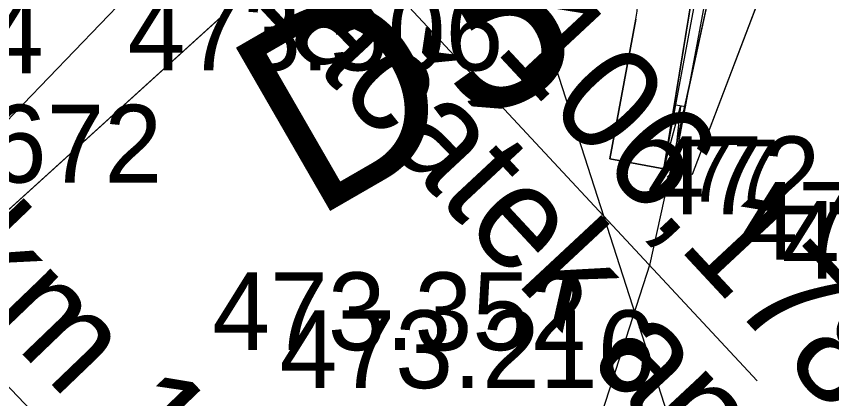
# Model space of a CAD drawing. Extents: x -758836 to -757729, y -1175316 to -1174366.
# Drawn here: x -758407.11 to -758394.53, y -1174860.8 to -1174854.9 of the extents above; entities that cross this region are included whole.
import ezdxf

# ---------------------------------------------------------------- set-up
doc = ezdxf.new("R2010")
doc.units = 0
for name, color, linetype in [('__NOR-dočasný zábor', 7, 'Continuous'), ('__NOR-trvalý zábor', 7, 'Continuous'), ('_NOR-návrh silná', 7, 'Continuous'), ('_NOR-návrh tenká', 7, 'Continuous'), ('_NOR-popis', 7, 'Continuous'), ('_vytyčený bod', 7, 'Continuous'), ('G_Obvod stavby', 7, 'Continuous'), ('Hranice parcel', 7, 'Continuous'), ('Vrstva 61', 7, 'Continuous')]:
    doc.layers.add(name, color=color, linetype=linetype)

msp = doc.modelspace()

# ---------------------------------------------------------------- linework, layer by layer
at = {"layer": '__NOR-dočasný zábor'}
for p, q in [((-758396.673, -1174857.339), (-758394.966, -1174852.852)), ((-758396.412, -1174852.941), (-758397.115, -1174857.256)), ((-758396.09, -1174853.08), (-758396.703, -1174855.869)), ((-758396.703, -1174855.869), (-758397.012, -1174857.276)), ((-758397.012, -1174857.276), (-758396.673, -1174857.339))]:
    msp.add_line(p, q, dxfattribs=at)
msp.add_lwpolyline([(-758397.115, -1174857.256), (-758397.951, -1174857.1), (-758397.548, -1174854.945)], dxfattribs=at)
msp.add_arc((-758399.514, -1174854.577), 2, 349.3996, 45, dxfattribs=at)
at = {"layer": '__NOR-trvalý zábor'}
for p, q in [((-758397.115, -1174857.256), (-758396.412, -1174852.941)), ((-758396.09, -1174853.08), (-758396.703, -1174855.869)), ((-758396.703, -1174855.869), (-758396.798, -1174856.299)), ((-758396.798, -1174856.299), (-758396.921, -1174856.86)), ((-758396.921, -1174856.86), (-758397.012, -1174857.276)), ((-758397.012, -1174857.276), (-758397.115, -1174857.256))]:
    msp.add_line(p, q, dxfattribs=at)
msp.add_arc((-758404.26, -1174852.758), 7.85, 358.6622, 358.6622, dxfattribs=at)
at = {"layer": '_NOR-návrh silná'}
msp.add_lwpolyline([(-758396.968, -1174857.284), (-758396.396, -1174854.23)], dxfattribs=at)
at = {"layer": '_NOR-návrh tenká'}
for p, q in [((-758408.177, -1174857.467), (-758403.548, -1174852.667)), ((-758397.115, -1174857.256), (-758396.858, -1174856.287)), ((-758396.858, -1174856.287), (-758396.968, -1174857.284)), ((-758396.784, -1174856.301), (-758396.931, -1174856.274))]:
    msp.add_line(p, q, dxfattribs=at)
for points in [[(-758396.968, -1174857.284), (-758396.673, -1174857.339), (-758390.499, -1174841.114), (-758389.088, -1174839.467), (-758389.316, -1174839.272)], [(-758396.968, -1174857.284), (-758397.115, -1174857.256), (-758396.544, -1174854.202)], [(-758397.115, -1174857.256), (-758397.951, -1174857.1), (-758397.548, -1174854.945)]]:
    msp.add_lwpolyline(points, dxfattribs=at)
msp.add_arc((-758399.514, -1174854.577), 2, 349.3996, 45, dxfattribs=at)
at = {"layer": '_NOR-popis'}
for p, q in [((-758403.828, -1174851.775), (-758395.679, -1174860.526)), ((-758403.828, -1174851.775), (-758395.679, -1174860.526)), ((-758410.061, -1174857.674), (-758401.913, -1174866.157)), ((-758410.061, -1174857.674), (-758401.913, -1174866.157))]:
    msp.add_line(p, q, dxfattribs=at)
msp.add_lwpolyline([(-758398.823, -1174886.544), (-758389.781, -1174883.631), (-758402.76, -1174843.338)], dxfattribs=at)
at = {"layer": '_vytyčený bod'}
for q in [(-758397.068, -1174857.184), (-758397.068, -1174857.384), (-758396.868, -1174857.184), (-758396.868, -1174857.384)]:
    msp.add_line((-758396.968, -1174857.284), q, dxfattribs=at)
at = {"layer": 'G_Obvod stavby'}
for p, q in [((-758397.548, -1174854.945), (-758397.951, -1174857.1)), ((-758397.951, -1174857.1), (-758397.115, -1174857.256))]:
    msp.add_line(p, q, dxfattribs=at)
for points in [[(-758397.115, -1174857.256), (-758396.673, -1174857.339), (-758394.966, -1174852.852), (-758392.882, -1174847.378), (-758392.028, -1174845.133), (-758391.423, -1174843.542), (-758390.499, -1174841.114), (-758389.088, -1174839.467), (-758389.316, -1174839.272), (-758390.315, -1174838.9)], [(-758457.56, -1174867.46), (-758444.33, -1174881.69), (-758438.77, -1174887.67), (-758435.375, -1174884.045), (-758431.98, -1174880.42), (-758414.84, -1174864.78), (-758400.066, -1174851.383)]]:
    msp.add_lwpolyline(points, dxfattribs=at)
msp.add_arc((-758399.514, -1174854.577), 2, 349.3996, 45, dxfattribs=at)
at = {"layer": 'Hranice parcel'}
for points in [[(-758398.4, -1174849.12), (-758399.71, -1174851.06), (-758414.84, -1174864.78), (-758431.98, -1174880.42)], [(-758410.71, -1174900.14), (-758397.33, -1174858.72), (-758396.09, -1174853.08), (-758397.47, -1174850.13)]]:
    msp.add_lwpolyline(points, dxfattribs=at)

# ---------------------------------------------------------------- texts
at = {"layer": '__NOR-dočasný zábor'}
msp.add_text('D3', height=2.9088, rotation=30, dxfattribs=at).set_placement((-758402.545, -1174858.065))
at = {"layer": '_NOR-popis'}
for s, rotation, p in [('km 106,178 779', 312.9634, (-758402.099, -1174852.898)), ('km 106,178 779', 312.9634, (-758402.099, -1174852.898)), ('začátek antikorozní úpravy upevňovadel', 312.9634, (-758403.709, -1174854.398)), ('začátek antikorozní úpravy upevňovadel', 312.9634, (-758403.709, -1174854.398)), ('km 106,170 091', 313.8418, (-758408.315, -1174858.77)), ('km 106,170 091', 313.8418, (-758408.315, -1174858.77)), ('řez a svár,', 313.8418, (-758409.901, -1174860.294)), ('řez a svár,', 313.8418, (-758409.901, -1174860.294))]:
    msp.add_text(s, height=1.59987, rotation=rotation, dxfattribs=at).set_placement(p)
at = {"layer": '_vytyčený bod'}
for height in [0.9599, 0.9596]:
    msp.add_text('77', height=height, dxfattribs=at).set_placement((-758396.768, -1174857.764))
at = {"layer": 'Vrstva 61'}
for s, p in [('473.506', (-758405.396, -1174855.737)), ('473.144', (-758412.49, -1174855.783)), ('473.672', (-758410.662, -1174857.467)), ('472.915', (-758397.379, -1174857.956)), ('472.881', (-758395.939, -1174858.657)), ('472.856', (-758395.297, -1174858.949)), ('473.352', (-758404.089, -1174860.053)), ('473.216', (-758403.048, -1174860.639))]:
    msp.add_text(s, height=1.2, dxfattribs=at).set_placement(p)

doc.saveas('drawing.dxf')
